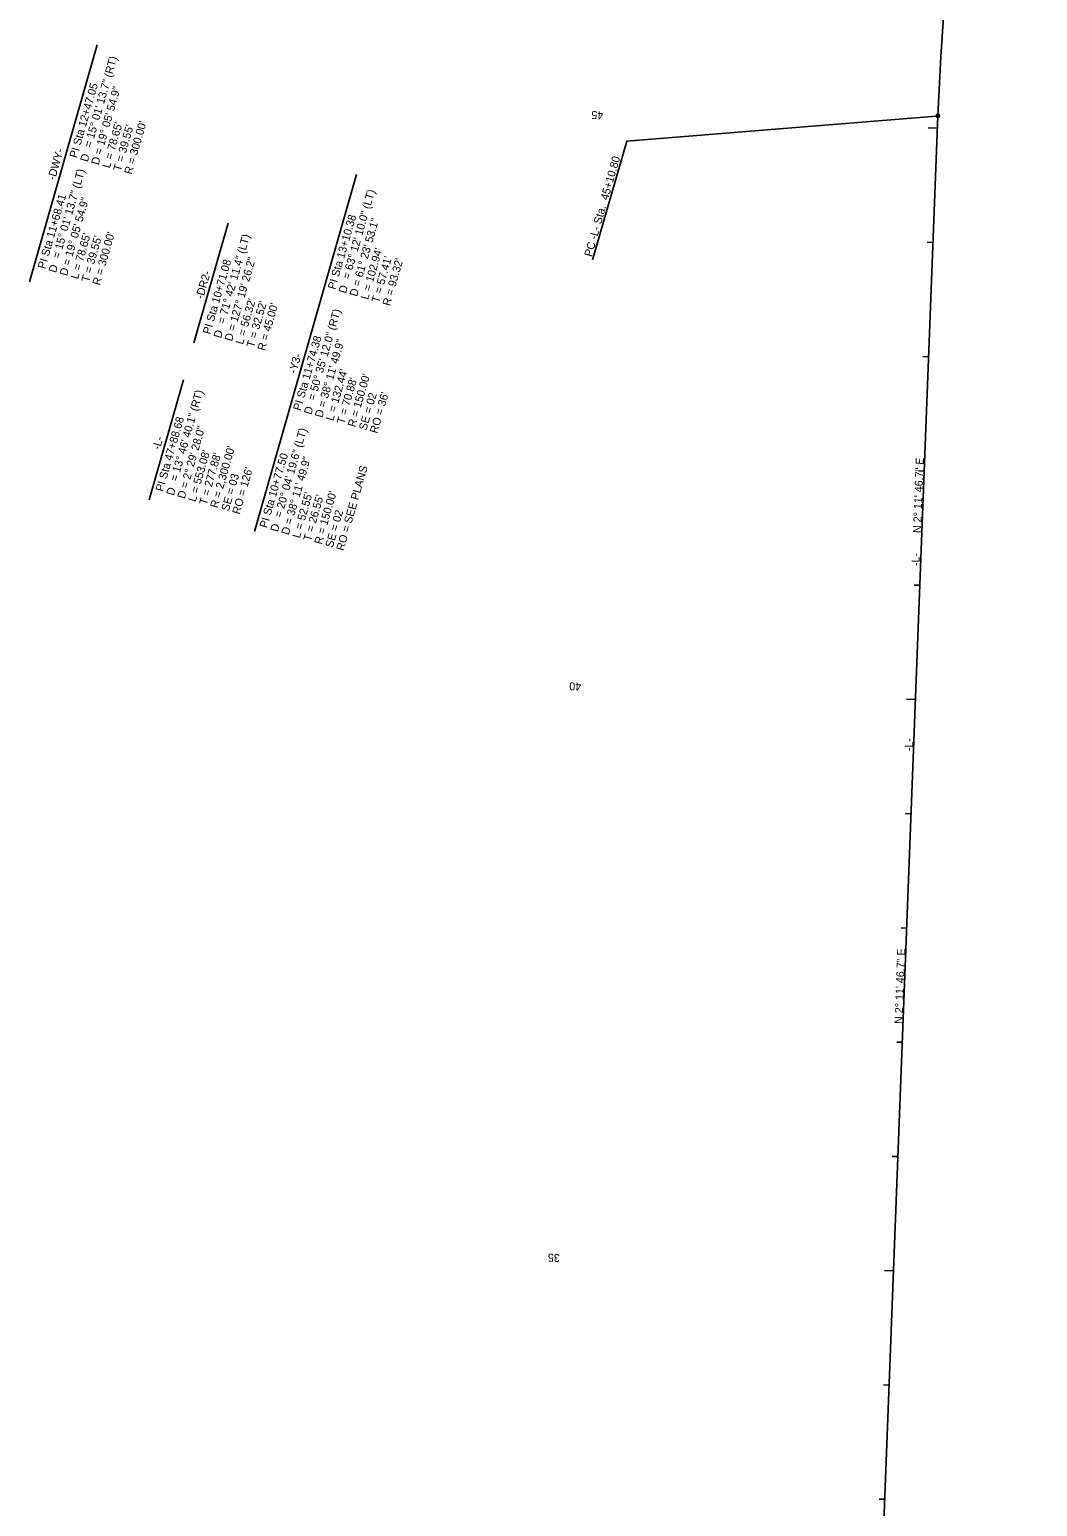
# Model space of a CAD drawing. Extents: x 2096901 to 2098386, y 684661 to 689731.
# Drawn here: x 2096991 to 2097872, y 687312 to 688604 of the extents above; entities that cross this region are included whole.
import ezdxf

# ---------------------------------------------------------------- set-up
doc = ezdxf.new("R2010")
doc.units = 0
for name, color, linetype in [('Prop Horizontal Alignment', 7, 'Continuous'), ('Prop Horizontal Alignment Curve and Spiral Data', 7, 'Continuous'), ('Prop Horizontal Alignment Direction Label', 7, 'Continuous'), ('Prop Horizontal Alignment Station Label', 7, 'Continuous'), ('Prop Horizontal Alignment Tick Label', 7, 'Continuous'), ('Prop Horizontal Alignment Tick Large', 7, 'Continuous'), ('Prop Horizontal Alignment Tick Small', 7, 'Continuous'), ('Scratch_Level_3', 7, 'Continuous'), ('Scratch_Level_5', 7, 'Continuous')]:
    doc.layers.add(name, color=color, linetype=linetype)

msp = doc.modelspace()

# ---------------------------------------------------------------- linework, layer by layer
at = {"layer": 'Prop Horizontal Alignment'}
msp.add_line((2097726.6, 686999.7), (2097785.2, 688528.4), dxfattribs=at)
msp.add_arc((2100083.6, 688440.2), 2300, 164.0259, 177.8037, dxfattribs=at)
at = {"layer": 'Prop Horizontal Alignment Curve and Spiral Data'}
for p, q in [((2096990.5, 688383.3), (2097049.8, 688590.4)), ((2097187.3, 688164.9), (2097276.7, 688477.1)), ((2097134.4, 688329.8), (2097164.4, 688434.6)), ((2097095.2, 688192.7), (2097125.2, 688297.5))]:
    msp.add_line(p, q, dxfattribs=at)
at = {"layer": 'Prop Horizontal Alignment Station Label'}
for p in [(2097783.8, 688528.2), (2097483.2, 688402.5)]:
    msp.add_line(p, (2097513, 688506.4), dxfattribs=at)
msp.add_circle((2097785.2, 688528.4), 1.5, dxfattribs=at)
at = {"layer": 'Prop Horizontal Alignment Tick Large'}
for p, q in [((2097784.8, 688517.6), (2097776.8, 688517.9)), ((2097765.7, 688018), (2097757.7, 688018.3)), ((2097746.5, 687518.3), (2097738.5, 687518.6))]:
    msp.add_line(p, q, dxfattribs=at)
at = {"layer": 'Prop Horizontal Alignment Tick Small'}
for p, q in [((2097781, 688417.7), (2097776, 688417.9)), ((2097777.2, 688317.7), (2097772.2, 688317.9)), ((2097773.3, 688217.8), (2097768.3, 688218)), ((2097769.5, 688117.9), (2097764.5, 688118.1)), ((2097761.8, 687918), (2097756.8, 687918.2)), ((2097758, 687818.1), (2097753, 687818.3)), ((2097754.2, 687718.2), (2097749.2, 687718.4)), ((2097750.3, 687618.3), (2097745.3, 687618.4)), ((2097742.7, 687418.4), (2097737.7, 687418.6)), ((2097738.8, 687318.5), (2097733.9, 687318.7))]:
    msp.add_line(p, q, dxfattribs=at)
at = {"layer": 'Scratch_Level_3'}
msp.add_line((2097726.6, 686999.7), (2097785.2, 688528.4), dxfattribs=at)
at = {"layer": 'Scratch_Level_5'}
msp.add_arc((2100083.6, 688440.2), 2300, 164.0259, 177.8037, dxfattribs=at)

# ---------------------------------------------------------------- texts
at = {"layer": 'Prop Horizontal Alignment Curve and Spiral Data'}
for s, p in [('= 15%%d 01\' 13.7" (RT)', (2097044.7, 688500.2)), ('PI Sta 12+47.05', (2097032, 688491.1)), ('D = 19%%d 05\' 54.9"', (2097051, 688485)), ("L = 78.65'", (2097060.7, 688482.2)), ("T = 39.55'", (2097070.3, 688479.5)), ("R = 300.00'", (2097079.9, 688476.7)), ('-DWY-', (2097012.8, 688471.7)), ('D', (2097041.4, 688487.7)), ('= 15%%d 01\' 13.7" (LT)', (2097016.9, 688403.1)), ('PI Sta 11+68.41', (2097004.2, 688394.1)), ('D = 19%%d 05\' 54.9"', (2097023.3, 688388)), ('= 63%%d 12\' 10.0" (LT)', (2097270.7, 688385.1)), ('PI Sta 13+10.38', (2097258, 688376.1)), ('D = 61%%d 23\' 53.1"', (2097277, 688369.9)), ("L = 78.65'", (2097032.9, 688385.2)), ("T = 39.55'", (2097042.5, 688382.4)), ("R = 300.00'", (2097052.1, 688379.7)), ('= 71%%d 42\' 11.4" (LT)', (2097161.3, 688346)), ('D = 127%%d 19\' 26.2"', (2097167.7, 688330.8)), ("L = 102.94'", (2097286.7, 688367.2)), ("T = 57.41'", (2097296.3, 688364.4)), ("R = 93.32'", (2097305.9, 688361.7)), ('D', (2097013.7, 688390.7)), ('-DR2-', (2097142.3, 688367.7)), ('PI Sta 10+71.08', (2097148.6, 688336.9)), ('D', (2097267.4, 688372.7)), ("L = 56.32'", (2097177.3, 688328)), ("T = 32.52'", (2097186.9, 688325.3)), ("R = 45.00'", (2097196.5, 688322.5)), ('= 50%%d 35\' 12.0" (RT)', (2097240.3, 688279.1)), ('D', (2097158.1, 688333.5)), ('PI Sta 11+74.38', (2097227.7, 688270.1)), ('D = 38%%d 11\' 49.9"', (2097246.7, 688264)), ('-Y3-', (2097223.7, 688302.5)), ("L = 132.44'", (2097256.3, 688261.2)), ("R = 150.00'", (2097275.5, 688255.7)), ('= 13%%d 46\' 40.1" (RT)', (2097119.9, 688208.3)), ("T = 70.88'", (2097265.9, 688258.4)), ('SE = 02', (2097285.2, 688252.9)), ("RO = 36'", (2097294.8, 688250.2)), ('PI Sta 47+88.68', (2097107.3, 688199.3)), ('D', (2097237.1, 688266.7)), ('D = 2%%d 29\' 28.0"', (2097126.3, 688193.1)), ('= 20%%d 04\' 19.6" (LT)', (2097211, 688176.5)), ('-L-', (2097104.5, 688235.9)), ("L = 553.08'", (2097135.9, 688190.4)), ("R = 2,300.00'", (2097155.1, 688184.9)), ("T = 277.88'", (2097145.5, 688187.6)), ('PI Sta 10+77.50', (2097198.3, 688167.5)), ('D = 38%%d 11\' 49.9"', (2097217.3, 688161.4)), ('SE = 03', (2097164.8, 688182.1)), ("RO = 126'", (2097174.4, 688179.4)), ('RO = SEE PLANS', (2097265.4, 688147.6)), ('D', (2097116.7, 688195.9)), ("L = 52.55'", (2097227, 688158.6)), ("T = 26.55'", (2097236.6, 688155.9)), ("R = 150.00'", (2097246.2, 688153.1)), ('D', (2097207.7, 688164.1)), ('SE = 02', (2097255.8, 688150.3))]:
    msp.add_text(s, height=7, rotation=74.0259, dxfattribs=at).set_placement(p)
at = {"layer": 'Prop Horizontal Alignment Direction Label'}
for p in [(2097770.4, 688163.4), (2097754.2, 687734.1)]:
    msp.add_text('N 2%%d 11\' 46.7" E', height=7, rotation=87.8037, dxfattribs=at).set_placement(p)
at = {"layer": 'Prop Horizontal Alignment Station Label'}
for s, rotation, p in [('PC -L- Sta.  45+10.80', 74.0259, (2097482.4, 688404.7)), ('-L-', 88.3348, (2097769.1, 688134.6)), ('-L-', 88.3348, (2097763.1, 687972.7))]:
    msp.add_text(s, height=7, rotation=rotation, dxfattribs=at).set_placement(p)
at = {"layer": 'Prop Horizontal Alignment Tick Label'}
for s, p in [('45', (2097492.6, 688532.3)), ('40', (2097473.3, 688032.7)), ('35', (2097454.6, 687533))]:
    msp.add_text(s, height=7, rotation=177.8037, dxfattribs=at).set_placement(p)

doc.saveas('drawing.dxf')
